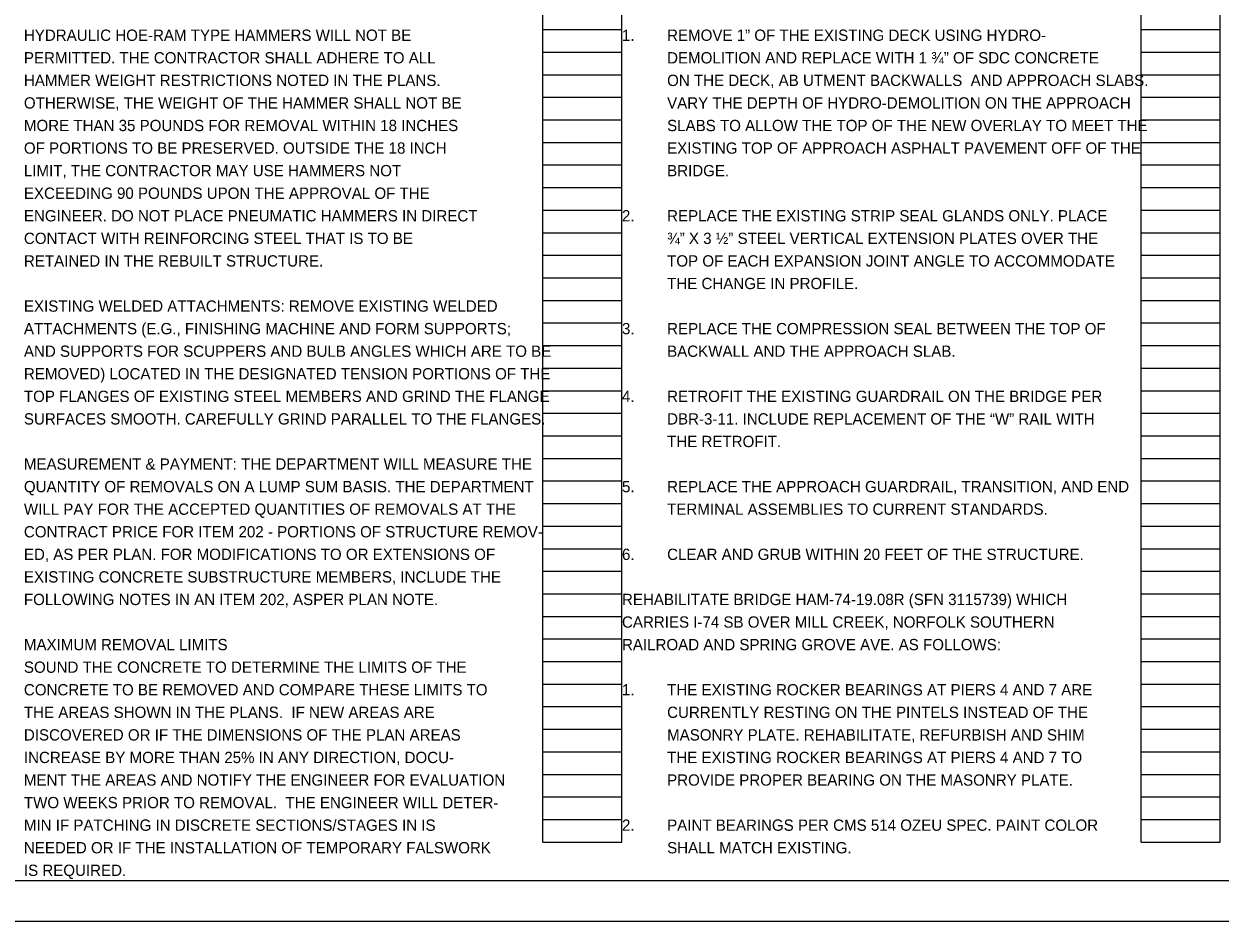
# Model space of a CAD drawing. Extents: x -11.4 to 50.8, y -16 to 31.7.
# Drawn here: x 9.82 to 24.66, y 0 to 11.13 of the extents above; entities that cross this region are included whole.
import ezdxf

# ---------------------------------------------------------------- set-up
doc = ezdxf.new("R2010")
doc.units = 0
for name, color, linetype in [('SC_Scratch1', 7, 'Continuous'), ('SH_Border', 7, 'Continuous'), ('SH_Cut_Line', 7, 'Continuous'), ('SH_Text', 7, 'Continuous')]:
    doc.layers.add(name, color=color, linetype=linetype)

msp = doc.modelspace()

# ---------------------------------------------------------------- linework, layer by layer
at = {"layer": 'SC_Scratch1'}
for p, q in [((16.26, 0.98), (16.26, 21.14)), ((17.24, 0.98), (17.24, 21.14)), ((23.68, 0.98), (23.68, 21.14)), ((24.66, 0.98), (24.66, 21.14)), ((16.26, 11.06), (17.24, 11.06)), ((23.68, 11.06), (24.66, 11.06)), ((16.26, 10.78), (17.24, 10.78)), ((23.68, 10.78), (24.66, 10.78)), ((16.26, 10.5), (17.24, 10.5)), ((23.68, 10.5), (24.66, 10.5)), ((16.26, 10.22), (17.24, 10.22)), ((23.68, 10.22), (24.66, 10.22)), ((16.26, 9.94), (17.24, 9.94)), ((23.68, 9.94), (24.66, 9.94)), ((16.26, 9.66), (17.24, 9.66)), ((23.68, 9.66), (24.66, 9.66)), ((16.26, 9.38), (17.24, 9.38)), ((23.68, 9.38), (24.66, 9.38)), ((16.26, 9.1), (17.24, 9.1)), ((23.68, 9.1), (24.66, 9.1)), ((16.26, 8.82), (17.24, 8.82)), ((23.68, 8.82), (24.66, 8.82)), ((16.26, 8.54), (17.24, 8.54)), ((23.68, 8.54), (24.66, 8.54)), ((16.26, 8.26), (17.24, 8.26)), ((23.68, 8.26), (24.66, 8.26)), ((16.26, 7.98), (17.24, 7.98)), ((23.68, 7.98), (24.66, 7.98)), ((16.26, 7.7), (17.24, 7.7)), ((23.68, 7.7), (24.66, 7.7)), ((16.26, 7.42), (17.24, 7.42)), ((23.68, 7.42), (24.66, 7.42)), ((16.26, 7.14), (17.24, 7.14)), ((23.68, 7.14), (24.66, 7.14)), ((16.26, 6.86), (17.24, 6.86)), ((23.68, 6.86), (24.66, 6.86)), ((16.26, 6.58), (17.24, 6.58)), ((23.68, 6.58), (24.66, 6.58)), ((16.26, 6.3), (17.24, 6.3)), ((23.68, 6.3), (24.66, 6.3)), ((16.26, 6.02), (17.24, 6.02)), ((23.68, 6.02), (24.66, 6.02)), ((16.26, 5.74), (17.24, 5.74)), ((23.68, 5.74), (24.66, 5.74)), ((16.26, 5.46), (17.24, 5.46)), ((23.68, 5.46), (24.66, 5.46)), ((16.26, 5.18), (17.24, 5.18)), ((23.68, 5.18), (24.66, 5.18)), ((16.26, 4.9), (17.24, 4.9)), ((23.68, 4.9), (24.66, 4.9)), ((16.26, 4.62), (17.24, 4.62)), ((23.68, 4.62), (24.66, 4.62)), ((16.26, 4.34), (17.24, 4.34)), ((23.68, 4.34), (24.66, 4.34)), ((16.26, 4.06), (17.24, 4.06)), ((23.68, 4.06), (24.66, 4.06)), ((16.26, 3.78), (17.24, 3.78)), ((23.68, 3.78), (24.66, 3.78)), ((16.26, 3.5), (17.24, 3.5)), ((23.68, 3.5), (24.66, 3.5)), ((16.26, 3.22), (17.24, 3.22)), ((23.68, 3.22), (24.66, 3.22)), ((16.26, 2.94), (17.24, 2.94)), ((23.68, 2.94), (24.66, 2.94)), ((16.26, 2.66), (17.24, 2.66)), ((23.68, 2.66), (24.66, 2.66)), ((16.26, 2.38), (17.24, 2.38)), ((23.68, 2.38), (24.66, 2.38)), ((16.26, 2.1), (17.24, 2.1)), ((23.68, 2.1), (24.66, 2.1)), ((16.26, 1.82), (17.24, 1.82)), ((23.68, 1.82), (24.66, 1.82)), ((16.26, 1.54), (17.24, 1.54)), ((23.68, 1.54), (24.66, 1.54)), ((16.26, 1.26), (17.24, 1.26)), ((23.68, 1.26), (24.66, 1.26)), ((16.26, 0.98), (17.24, 0.98)), ((23.68, 0.98), (24.66, 0.98))]:
    msp.add_line(p, q, dxfattribs=at)
at = {"layer": 'SH_Border'}
msp.add_lwpolyline([(1.5, 21.5), (33.5, 21.5), (33.5, 0.5), (1.5, 0.5)], close=True, dxfattribs=at)
at = {"layer": 'SH_Cut_Line'}
msp.add_lwpolyline([(0, 0), (34, 0), (34, 22), (0, 22)], close=True, dxfattribs=at)

# ---------------------------------------------------------------- texts
at = {"layer": 'SH_Text'}
for s, p in [('HYDRAULIC HOE-RAM TYPE HAMMERS WILL NOT BE', (9.82, 10.92)), ('1.', (17.24, 10.92)), ('REMOVE 1” OF THE EXISTING DECK USING HYDRO-', (17.8, 10.92)), ('PERMITTED. THE CONTRACTOR SHALL ADHERE TO ALL ', (9.82, 10.64)), ('DEMOLITION AND REPLACE WITH 1 ¾” OF SDC CONCRETE', (17.8, 10.64)), ('HAMMER WEIGHT RESTRICTIONS NOTED IN THE PLANS.', (9.82, 10.36)), ('ON THE DECK, AB UTMENT BACKWALLS  AND APPROACH SLABS.', (17.8, 10.36)), ('OTHERWISE, THE WEIGHT OF THE HAMMER SHALL NOT BE', (9.82, 10.08)), ('VARY THE DEPTH OF HYDRO-DEMOLITION ON THE APPROACH', (17.8, 10.08)), ('MORE THAN 35 POUNDS FOR REMOVAL WITHIN 18 INCHES', (9.82, 9.8)), ('SLABS TO ALLOW THE TOP OF THE NEW OVERLAY TO MEET THE', (17.8, 9.8)), ('OF PORTIONS TO BE PRESERVED. OUTSIDE THE 18 INCH', (9.82, 9.52)), ('EXISTING TOP OF APPROACH ASPHALT PAVEMENT OFF OF THE', (17.8, 9.52)), ('LIMIT, THE CONTRACTOR MAY USE HAMMERS NOT', (9.82, 9.24)), ('BRIDGE. ', (17.8, 9.24)), ('EXCEEDING 90 POUNDS UPON THE APPROVAL OF THE', (9.82, 8.96)), ('ENGINEER. DO NOT PLACE PNEUMATIC HAMMERS IN DIRECT', (9.82, 8.68)), ('2.', (17.24, 8.68)), ('REPLACE THE EXISTING STRIP SEAL GLANDS ONLY. PLACE', (17.8, 8.68)), ('CONTACT WITH REINFORCING STEEL THAT IS TO BE', (9.82, 8.4)), ('¾” X 3 ½” STEEL VERTICAL EXTENSION PLATES OVER THE', (17.8, 8.4)), ('RETAINED IN THE REBUILT STRUCTURE.', (9.82, 8.12)), ('TOP OF EACH EXPANSION JOINT ANGLE TO ACCOMMODATE', (17.8, 8.12)), ('THE CHANGE IN PROFILE. ', (17.8, 7.84)), ('EXISTING WELDED ATTACHMENTS: REMOVE EXISTING WELDED', (9.82, 7.56)), ('ATTACHMENTS (E.G., FINISHING MACHINE AND FORM SUPPORTS;', (9.82, 7.28)), ('3.', (17.24, 7.28)), ('REPLACE THE COMPRESSION SEAL BETWEEN THE TOP OF', (17.8, 7.28)), ('AND SUPPORTS FOR SCUPPERS AND BULB ANGLES WHICH ARE TO BE', (9.82, 7)), ('BACKWALL AND THE APPROACH SLAB.', (17.8, 7)), ('REMOVED) LOCATED IN THE DESIGNATED TENSION PORTIONS OF THE', (9.82, 6.72)), ('TOP FLANGES OF EXISTING STEEL MEMBERS AND GRIND THE FLANGE', (9.82, 6.44)), ('4.', (17.24, 6.44)), ('RETROFIT THE EXISTING GUARDRAIL ON THE BRIDGE PER', (17.8, 6.44)), ('SURFACES SMOOTH. CAREFULLY GRIND PARALLEL TO THE FLANGES.', (9.82, 6.16)), ('DBR-3-11. INCLUDE REPLACEMENT OF THE “W” RAIL WITH', (17.8, 6.16)), ('THE RETROFIT.', (17.8, 5.88)), ('MEASUREMENT & PAYMENT: THE DEPARTMENT WILL MEASURE THE', (9.82, 5.6)), ('QUANTITY OF REMOVALS ON A LUMP SUM BASIS. THE DEPARTMENT', (9.82, 5.32)), ('5.', (17.24, 5.32)), ('REPLACE THE APPROACH GUARDRAIL, TRANSITION, AND END', (17.8, 5.32)), ('WILL PAY FOR THE ACCEPTED QUANTITIES OF REMOVALS AT THE', (9.82, 5.04)), ('TERMINAL ASSEMBLIES TO CURRENT STANDARDS.  ', (17.8, 5.04)), ('CONTRACT PRICE FOR ITEM 202 - PORTIONS OF STRUCTURE REMOV-', (9.82, 4.76)), ('ED, AS PER PLAN. FOR MODIFICATIONS TO OR EXTENSIONS OF', (9.82, 4.48)), ('6.', (17.24, 4.48)), ('CLEAR AND GRUB WITHIN 20 FEET OF THE STRUCTURE.', (17.8, 4.48)), ('EXISTING CONCRETE SUBSTRUCTURE MEMBERS, INCLUDE THE', (9.82, 4.2)), ('FOLLOWING NOTES IN AN ITEM 202, ASPER PLAN NOTE.', (9.82, 3.92)), ('REHABILITATE BRIDGE HAM-74-19.08R (SFN 3115739) WHICH ', (17.24, 3.92)), ('CARRIES I-74 SB OVER MILL CREEK, NORFOLK SOUTHERN', (17.24, 3.64)), ('MAXIMUM REMOVAL LIMITS', (9.82, 3.36)), ('RAILROAD AND SPRING GROVE AVE. AS FOLLOWS:', (17.24, 3.36)), ('SOUND THE CONCRETE TO DETERMINE THE LIMITS OF THE', (9.82, 3.08)), ('CONCRETE TO BE REMOVED AND COMPARE THESE LIMITS TO', (9.82, 2.8)), ('1.', (17.24, 2.8)), ('THE EXISTING ROCKER BEARINGS AT PIERS 4 AND 7 ARE', (17.8, 2.8)), ('THE AREAS SHOWN IN THE PLANS.  IF NEW AREAS ARE', (9.82, 2.52)), ('CURRENTLY RESTING ON THE PINTELS INSTEAD OF THE', (17.8, 2.52)), ('DISCOVERED OR IF THE DIMENSIONS OF THE PLAN AREAS', (9.82, 2.24)), ('MASONRY PLATE. REHABILITATE, REFURBISH AND SHIM', (17.8, 2.24)), ('INCREASE BY MORE THAN 25% IN ANY DIRECTION, DOCU-', (9.82, 1.96)), ('THE EXISTING ROCKER BEARINGS AT PIERS 4 AND 7 TO', (17.8, 1.96)), ('MENT THE AREAS AND NOTIFY THE ENGINEER FOR EVALUATION', (9.82, 1.68)), ('PROVIDE PROPER BEARING ON THE MASONRY PLATE. ', (17.8, 1.68)), ('TWO WEEKS PRIOR TO REMOVAL.  THE ENGINEER WILL DETER-', (9.82, 1.4)), ('MIN IF PATCHING IN DISCRETE SECTIONS/STAGES IN IS', (9.82, 1.12)), ('2.', (17.24, 1.12)), ('PAINT BEARINGS PER CMS 514 OZEU SPEC. PAINT COLOR', (17.8, 1.12)), ('NEEDED OR IF THE INSTALLATION OF TEMPORARY FALSWORK', (9.82, 0.84)), ('SHALL MATCH EXISTING.', (17.8, 0.84)), ('IS REQUIRED.', (9.82, 0.56))]:
    msp.add_text(s, height=0.14, dxfattribs=at).set_placement(p)

doc.saveas('drawing.dxf')
